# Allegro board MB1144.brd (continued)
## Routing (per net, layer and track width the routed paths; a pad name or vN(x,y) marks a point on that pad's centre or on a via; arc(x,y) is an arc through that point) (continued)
VDD_ADJ: length 204.3
  TOP w0.508: 45.31,21.16 C131.1 ; C131.1 44.56,21.97 ; C131.1 45.31,22.78 ; C133.1 45.69,20.78 ; C133.1 45.23,20.32 ; C133.1 45.69,19.86 ; R236.1 43.91,19.75 ; R236.1 44.49,19.18 ; R236.1 43.33,19.18 ; 45.65,19.01 U34.4 45.12,18.6 ; JP2.3 36.16,156.08 32.23,156.08 30.96,154.81 30.96,148.21 22.07,139.32 22.07,135.05 21.48,134.47 21.48,130.81 v3(20.97,130.3) ; v3(50.01,30.86) 51.66,32.51 51.66,38.99 46.58,44.07 30.83,44.07 28.92,45.97 22.45,45.97 v3(21.94,46.48)
  BOTTOM w0.508: v3(50.01,30.86) 45.94,26.8 45.94,24.26 v3(45.43,23.75) v3(44.67,23.75) v3(43.91,23.75) 37.56,17.4 TP13.1 ; v3(21.94,46.48) 21.94,47.88 23.21,49.15 23.21,56.39 14.57,65.02 14.57,68.71 15.84,69.98 15.84,76.33 17.24,77.72 17.24,85.72 12.03,90.93 12.03,107.31 17.62,112.9 17.62,114.81 20.8,117.98 20.8,130.12 v3(20.97,130.3)
VDD_IO: length 93.7
  TOP w0.254: U7.95 61.25,140.48 62.22,141.45 62.22,143.48 C35.2
  TOP w0.279: U7.131 51.82,126.15 51.66,125.98 C46.1
  TOP w0.508: v1(39.97,141.1) 39.97,137.54 33.75,131.32 33.75,125.22 34.26,124.71 34.26,119.25 v1(36.29,117.22) ; v1(62.33,144.53) 61.82,144.02 C35.2 ; v1(41.88,121.41) 41.88,123.57 43.4,125.09 47.47,125.09 48.1,125.73 C46.1 ; v1(44.04,142.11) 44.04,147.83 46.32,150.11 49.12,150.11 JP3.2 TP4.1 v1(58.77,152.4)
  BOTTOM w0.508: v1(58.77,152.4) 58.77,147.45 59.66,146.56 62.07,146.56 62.45,146.18 62.45,144.65 v1(62.33,144.53) ; v1(36.29,117.22) 36.29,118.24 38.83,120.78 41.37,120.78 41.88,121.28 v1(41.88,121.41) ; v1(39.97,141.1) 40.99,142.11 v1(44.04,142.11)
VDD_MCU: length 80.4
  TOP w0.254: U7.84 66.75,141.75 C38.2 ; C43.2 50.26,130.94 51.66,130.94 51.87,131.15 U7.121 ; U7.144 47.99,119.65 C48.2
  TOP w0.279: 76.17,127.64 75.79,127.64 75.3,127.15 U7.52 ; U7.17 62.75,116.76 C51.2 ; C41.2 77.69,138.43 76.41,137.15 U7.72 ; 54.32,141.6 54.32,140.34 54.75,139.91 U7.108 ; U7.39 75.41,120.65 ; U7.62 75.09,132.15 75.09,132.14 77.37,132.14 77.82,131.7 C42.1
  TOP w0.508: 76.17,127.64 76.3,127.76 v3(76.3,128.78) ; v3(78.45,132.46) 78.71,132.21 C42.1 ; v3(79.6,139.19) 78.96,138.56 C41.2 ; v3(51.91,143.89) C32.1 53.05,142.88 54.32,141.6 ; C43.2 49.37,131.06 v3(49.12,130.81) ; 75.41,120.65 75.41,120.65 77.57,118.49 C50.2 v3(79.09,117.6) ; C48.2 v3(47.85,118.36) ; v3(33.3,105.71) 33.3,105.54 33.05,105.28 23.72,105.28 JP11.2 JP11.3 ; v3(62.71,115.82) 62.07,115.82 C51.2 ; C38.2 v3(65.5,140.72)
  BOTTOM w0.508: v3(47.85,118.36) 47.85,117.23 45.66,115.03 41.15,115.03 33.3,107.19 v3(33.3,105.71)
VDD_USB: length 39.5
  TOP w0.254: 55.59,140.97 55.59,140.34 55.72,140.21 55.72,139.23 U7.106
  TOP w0.508: 55.59,140.97 55.47,141.1 C36.2 C33.1 v1(54.32,143)
  BOTTOM w0.508: v1(54.32,143) 47.21,143 42.01,148.21 42.01,155.96 41.28,156.68 38.28,156.68 36.8,158.17 JP1.2 TP2.1
VDDA: length 39.9
  TOP w0.279: U7.33 70.75,118.61 71.52,119.38 v3(72.74,119.38)
  TOP w0.508: C60.2 88.06,106.17 ; C60.2 87.6,106.63 ; C60.2 87.6,105.71 ; 88.23,110.31 CN10.2 ; CN10.2 88.23,112.19 ; CN10.2 89.17,111.25 ; CN10.2 87.29,111.25 ; L1.2 91.79,106.88 ; L1.2 91.79,105.71 ; L1.2 91.17,106.3 ; C59.1 89.17,108.33 ; C59.1 87.55,108.33 ; C59.1 88.36,109.27 ; C59.1 88.36,107.39 ; 91.15,108.28 TP8.1 ; TP8.1 91.15,110.16 ; TP8.1 92.09,109.22 ; TP8.1 90.21,109.22
  BOTTOM w0.508: v3(72.74,119.38) 72.87,119.25 86.33,119.25 86.84,118.75 86.84,114.81 88.23,113.41 CN10.2
A0: length 208.7
  TOP w0.102: U5.E2 102.45,143.61 102.97,143.1 102.97,142.72 v4(102.84,142.6)
  TOP w0.127: v1(59.65,130.87) 58.9,130.12 58.9,127.13 59.25,126.77 U7.10 ; CN6.25 v1(28.16,121.41) ; U2.A3 82.94,152.3 82.61,152.63 81.6,152.63 80.92,153.31 v1(80.92,153.37) ; U21.47 53.39,70.44 52.67,69.72 51.78,69.72 51.02,70.48 35.66,70.48 v1(35.53,70.61)
  BOTTOM w0.127: v4(102.84,142.6) 102.97,142.72 102.97,143.62 102.86,143.73 102.86,148.31 101.34,149.83 101.34,152.83 99.92,154.25 99.92,157.35 97.12,160.15 91.99,160.15 89,157.15 89,154.81 88.77,154.58 84.22,154.58 83.61,155.19 82.14,155.19 81.12,154.18 81.12,153.64 80.92,153.44 v1(80.92,153.37) 80.87,153.31 80.87,153.29 80.36,152.78 79.34,152.78 77.31,150.75 77.31,142.11 73.73,138.53 72.84,138.53 71.09,136.78 71.09,136.17 66.74,131.83 60.6,131.83 v1(59.65,130.87) 57.81,129.03 46.96,129.03 46.58,129.41 44.29,129.41 44.04,129.16 39.08,129.16 32,122.07 28.82,122.07 v1(28.16,121.41) 26.64,119.89 26.64,111.63 27.74,110.53 27.74,101.57 26.77,100.6 26.77,98.04 26.48,97.76 26.48,95.25 27.07,94.67 27.07,93.19 29.76,90.5 29.76,77.39 30.68,76.48 30.68,74.95 33.5,72.14 34,72.14 v1(35.53,70.61)
A0_1DELAY: length 12.5
  TOP w0.127: U21.40 56.89,70.1 56.61,69.82 v1(56.61,69.82) ; U21.2 53.39,65.32 v1(52.67,66.04)
  BOTTOM w0.127: 52.42,63.63 52.04,64.01 52.04,65.41 v1(52.67,66.04) 56.36,69.72 56.51,69.72 v1(56.61,69.82)
A0_2DELAY: length 3.8
  TOP w0.127: v1(56.48,62.31) 56.48,62.36 56.89,62.77 U21.9
  BOTTOM w0.127: 54.71,63.27 54.71,63.12 55.52,62.31 v1(56.48,62.31)
A1: length 225.2
  TOP w0.102: v4(101.77,142.49) 101.37,142.49 100.98,142.88 100.98,143.6 101.44,144.06 U5.D2
  TOP w0.127: v1(39.62,67.79) 43.15,64.26 48.41,64.26 52.04,60.63 58.29,60.63 58.72,61.06 v1(58.72,62.15) ; v1(81.55,153.37) 81.91,153.01 82.92,153.01 U2.A4 ; v1(59.65,130.17) 59.28,129.8 59.28,127.38 59.75,126.91 U7.11 ; CN6.26 v1(29.56,121.41) ; v1(59.15,69.6) 58.39,70.35 U21.37
  BOTTOM w0.127: v4(101.77,142.49) 101.77,142.6 101.8,142.62 101.8,143.54 102.58,144.32 102.58,148.08 100.96,149.71 100.96,152.65 99.54,154.08 99.54,157.18 96.95,159.77 92.17,159.77 89.38,156.97 89.38,156.26 89.25,156.13 89.25,155.63 89.22,155.6 89.22,154.71 88.82,154.31 84.04,154.31 83.41,154.94 82.9,154.94 82.77,154.81 82.39,154.81 81.76,154.18 81.76,153.62 81.55,153.42 v1(81.55,153.37) 81.5,153.31 81.5,153.29 80.61,152.4 79.6,152.4 77.69,150.5 77.69,141.94 73.91,138.15 73.02,138.15 71.6,136.73 71.6,136.42 71.62,136.4 71.62,136.09 66.97,131.44 60.92,131.44 v1(59.65,130.17) 58.13,128.65 46.7,128.65 46.32,129.03 44.8,129.03 44.55,128.78 39.34,128.78 31.97,121.41 v1(29.56,121.41) 28.92,121.41 27.02,119.51 27.02,111.89 28.12,110.79 28.12,101.3 27.15,100.33 27.15,97.79 26.86,97.51 26.86,95.41 27.45,94.82 27.45,93.37 30.14,90.68 30.14,77.56 31.12,76.58 31.12,75.27 33.75,72.64 34.77,72.64 v1(39.62,67.79) ; v1(58.72,62.15) 58.13,62.74 58.13,64.14 SB51.1 58.9,67.56 59.15,67.82 v1(59.15,69.6)
A1_1DELAY: length 4.5
  TOP w0.127: v1(59.89,65.81) 58.74,65.81 58.39,65.46 U21.12
  BOTTOM w0.127: SB50.1 60.29,65.41 v1(59.89,65.81)
A1_BUF: length 31.2
  TOP w0.127: U22.24 82.68,65.12 82.39,65.41 71.85,65.41 71.18,64.73 U22.1 71.18,62.58 R166.2 68.75,62.1 67.05,60.4 62.5,60.4 v1(61.94,60.96)
  BOTTOM w0.127: v1(61.94,60.96) 61.94,63.04 61.61,63.37 58.9,63.37
A2: length 129
  TOP w0.102: v1(82.26,153.92) 82.41,153.78 U2.A5 ; v4(99.92,143.59) 99.96,143.62 99.99,143.62 100.43,144.06 U5.C2
  TOP w0.127: v1(61.31,130.81) 61.18,130.81 60.25,129.88 U7.12 ; CN6.32 v1(29.43,117.6)
  BOTTOM w0.127: v4(99.92,143.59) 99.94,143.59 99.98,143.62 101.43,143.62 102.2,144.4 102.2,147.96 99.97,150.19 99.97,151.76 99.16,152.58 99.16,157 96.77,159.38 92.35,159.38 89.76,156.79 89.76,156.08 89.63,155.96 89.63,155.45 89.5,155.32 89.5,154.56 88.97,154.03 83.94,154.03 83.79,154.18 82.52,154.18 v1(82.26,153.92) 82.26,153.03 81.88,152.65 81.5,152.65 80.87,152.02 79.98,152.02 78.07,150.11 78.07,141.76 74.09,137.77 73.2,137.77 72,136.58 72,135.92 67.15,131.06 61.56,131.06 v1(61.31,130.81) 60.93,130.81 58.39,128.27 52.93,128.27 51.86,127.2 40.05,127.2 30.45,117.6 v1(29.43,117.6)
A3: length 130.5
  TOP w0.102: U5.A2 98,143.61 v4(97.99,143.61)
  TOP w0.127: v1(81.96,152.17) 82.24,151.89 83.15,151.89 83.41,152.15 83.56,152.15 U2.B3 ; v1(61.31,130.18) 60.75,129.61 U7.13 ; CN6.34 v1(29.43,116.33)
  BOTTOM w0.127: v4(97.99,143.61) 98.44,143.15 99.13,143.15 99.4,143.42 99.4,143.68 99.76,144.04 100.5,144.04 100.65,143.89 101.37,143.89 101.9,144.42 101.9,147.5 99.59,149.81 99.59,151.59 98.77,152.4 98.77,156.82 96.59,159 92.53,159 90.14,156.62 90.14,155.91 90.01,155.78 90.01,155.37 89.73,155.09 89.73,154.46 89,153.72 83.51,153.72 v1(81.96,152.17) 81.63,152.17 81.1,151.64 80.16,151.64 78.45,149.94 78.45,141.58 74.26,137.39 73.37,137.39 72.38,136.4 72.38,135.74 67.33,130.68 61.82,130.68 v1(61.31,130.18) 60.93,130.18 58.64,127.89 53.69,127.89 51.78,125.98 50.51,125.98 50.13,125.6 39.72,125.6 30.45,116.33 v1(29.43,116.33)
A4: length 127.3
  TOP w0.102: U2.B4 83.69,152.94 83.41,152.65 v5(83.33,152.65) ; U5.B2 v4(98.99,143.6)
  TOP w0.127: CN6.37 27.4,113.79 v1(28.29,114.68) ; U7.14 61.25,129.48 v1(61.31,129.54)
  BOTTOM w0.127: v4(98.99,143.6) 99.76,144.37 100.5,144.37 100.76,144.12 101.26,144.12 101.64,144.5 101.64,147.36 99.21,149.8 99.21,151.41 98.39,152.22 98.39,156.64 96.41,158.62 92.7,158.62 90.52,156.44 90.52,155.73 90.39,155.6 90.39,155.19 90.04,154.84 90.04,154.43 89,153.39 84.07,153.39 v5(83.33,152.65) 83.08,152.65 82.14,151.71 81.73,151.71 81.27,151.26 80.33,151.26 78.84,149.76 78.84,141.4 67.74,130.3 62.07,130.3 v1(61.31,129.54) 59.28,127.51 53.94,127.51 51.28,124.84 40.23,124.84 30.19,114.81 28.42,114.81 v1(28.29,114.68)
A5: length 121.8
  TOP w0.102: v5(84.84,152.65) 84.47,152.28 U2.C3
  TOP w0.127: CN6.38 30.32,113.79 v1(29.81,114.3) ; U5.D3 101.45,145.04 v4(100.93,144.53) ; v1(62.07,129.54) 61.75,129.22 U7.15
  BOTTOM w0.127: v4(100.93,144.53) 101.39,144.98 101.39,147.19 98.83,149.76 98.83,151.23 98.01,152.04 98.01,156.46 96.23,158.24 92.88,158.24 90.9,156.26 90.9,155.37 90.32,154.79 90.32,154.31 89.12,153.11 85.3,153.11 v5(84.84,152.65) 84.17,152.65 83.71,152.2 83.03,152.2 82.16,151.33 81.91,151.33 81.45,150.88 80.51,150.88 79.22,149.58 79.22,141.22 67.91,129.92 62.45,129.92 v1(62.07,129.54) 59.66,127.13 54.1,127.13 51.43,124.46 40.61,124.46 30.45,114.3 v1(29.81,114.3)
A6: length 98.6
  TOP w0.102: U5.C3 100,145.06 99.4,144.45 98.11,144.45 97.91,144.25 97.35,144.25 v1(97.12,144.02)
  TOP w0.127: U2.C4 84.44,152.8 84.07,152.43 84.07,152.16 83.79,151.88 83.55,151.88 83.34,151.68 83.34,151.43 83.04,151.13 82.8,151.13 82.52,150.85 82.52,149.05 81.5,148.03 v4(81.4,148.03) ; CN7.17 v1(97.12,126.49) ; v1(71.98,128.52) 71.98,126.9 72.73,126.15 U7.50
  BOTTOM w0.127: v1(97.12,144.02) 96.92,144.22 96.92,147.96 96.11,148.77 96.11,155.57 95.35,156.34 93.77,156.34 92.81,155.37 92.81,154.48 92.27,153.95 92.27,153.72 89.94,151.38 87.42,151.38 87.04,151 85.82,151 85.69,151.13 84.55,151.13 84.17,150.75 84.17,150.62 81.58,148.03 v4(81.4,148.03) 81.12,147.75 81.12,138.73 79.75,137.36 78.15,137.36 73.6,132.82 73.6,132.51 73.63,132.49 73.63,131.44 71.98,129.79 v1(71.98,128.52) 72.1,128.4 72.74,128.4 73.25,127.89 74.9,127.89 75.41,127.38 90.77,127.38 91.66,126.49 v1(97.12,126.49)
A7: length 101.6
  TOP w0.102: v4(97.5,145.03) 97.53,145.06 U5.A3
  TOP w0.127: CN7.18 v1(98.27,126.49) ; v1(81.25,149.28) 81.22,149.3 81.22,150.14 79.09,152.27 79.09,153.92 79.34,154.18 81.38,154.18 82.14,153.42 84.68,153.42 85.06,153.03 U2.D4 ; U7.53 74.29,127.64 72.87,127.64 v1(72.61,127.89)
  BOTTOM w0.127: v4(97.5,145.03) 97.4,145.14 97.4,150.34 96.49,151.26 96.49,155.75 95.52,156.72 93.59,156.72 92.42,155.55 92.42,154.66 91.89,154.13 91.89,153.9 89.76,151.76 87.22,151.76 86.71,151.26 85.95,151.26 85.82,151.38 84.4,151.38 83.41,150.39 83.38,150.39 82.34,149.35 81.32,149.35 v1(81.25,149.28) 81.15,149.28 80.74,148.87 80.74,140.03 80.11,139.4 80.11,138.56 79.41,137.86 78.09,137.86 71.29,131.06 71.29,128.57 71.98,127.89 v1(72.61,127.89) 72.99,127.51 74.64,127.51 75.15,127 90.52,127 91.66,125.86 97.63,125.86 v1(98.27,126.49)
A8: length 76.7
  TOP w0.102: 96.87,147.59 98,147.59 98.11,147.47 98.86,147.47 U5.B6
  TOP w0.127: v1(72.49,129.41) 72.49,129.03 73.37,128.14 74.3,128.14 U7.54 ; 96.87,147.59 96.04,147.59 94.15,149.48 91.04,149.48 89.77,150.75 89.48,150.75 v4(89.3,150.93) 88.84,151.38 88.34,151.38 U2.H2 ; CN7.16 v1(98.14,127.76)
  BOTTOM w0.127: v4(89.3,150.93) 89.12,150.75 88.82,150.75 88.69,150.62 84.73,150.62 81.54,147.43 81.54,138.6 79.93,136.98 78.33,136.98 74.01,132.66 74.01,131.19 72.49,129.67 v1(72.49,129.41) 72.49,129.29 73.5,128.27 75.15,128.27 75.66,127.76 91.03,127.76 91.66,127.13 97.5,127.13 v1(98.14,127.76)
A9: length 74.8
  TOP w0.127: CN7.14 98.37,129.03 98.16,128.83 v1(98.16,128.73) ; v1(73.12,129.41) 73.12,129.03 73.51,128.65 U7.55 ; U5.A6 98.05,148.45 96.42,148.45 94.63,150.24 91.62,150.24 90.75,151.12 v4(90.75,151.33) 90.53,151.33 89.59,152.27 88.2,152.27 U2.H3
  BOTTOM w0.127: v1(98.16,128.73) 97.71,128.27 96.17,128.27 96.04,128.14 75.91,128.14 75.28,128.78 73.63,128.78 73.12,129.29 v1(73.12,129.41) 73.12,129.67 74.39,130.94 74.39,132.28 78.71,136.6 80.11,136.6 82.26,138.76 82.26,147.6 84.4,149.73 84.7,149.73 84.73,149.71 87.89,149.71 88.55,150.37 89.78,150.37 v4(90.75,151.33)
A10: length 75.1
  TOP w0.102: U5.C6 99.84,148.67 99.84,149.21 99.59,149.47 96.87,149.47
  TOP w0.127: v1(98.14,129.9) 98.55,130.3 CN7.12 ; U7.56 v1(75.53,129.15) ; 96.87,149.47 96.73,149.47 95.19,151 92.07,151 v4(91.97,151.1) 91.97,151.69 90.52,153.14 89.35,153.14 89.33,153.11 88.44,153.11 88.35,153.03 U2.H4
  BOTTOM w0.127: v4(91.97,151.1) 91.97,151.05 90.9,149.99 88.72,149.99 88.06,149.33 84.55,149.33 82.65,147.42 82.65,138.58 80.28,136.22 78.89,136.22 74.77,132.11 74.77,129.79 75.42,129.15 v1(75.53,129.15) 75.65,129.15 75.79,129.29 97.53,129.29 v1(98.14,129.9)
A11: length 85.6
  TOP w0.102: U5.D6 101.83,148.44 101.83,150.58 101.49,150.93 101.49,151.13
  TOP w0.127: v1(96.79,129.92) 96.41,130.3 CN7.11 ; U7.57 74.88,129.65 74.9,129.67 75.79,129.67 76.04,129.92 v1(76.17,129.92) ; 101.49,151.13 101.49,154.03 102.99,155.52 102.99,155.88 102.69,156.18 99.38,156.18 98.34,155.14 98.34,154.76 98.37,154.74 98.37,154.46 98.34,154.43 98.34,154.41 95.78,151.84 v4(93.21,151.84) 93.19,151.87 92.91,151.87 90.85,153.92 88.34,153.92 U2.H5
  BOTTOM w0.127: v4(93.21,151.84) 93.21,151.69 91.13,149.61 88.89,149.61 88.23,148.95 84.73,148.95 83.03,147.24 83.03,138.4 80.46,135.84 79.06,135.84 75.15,131.93 75.15,130.94 v1(76.17,129.92) v1(96.79,129.92)
A12: length 112.9
  TOP w0.102: U5.B7 98.89,148.5 98.89,147.96 98.61,147.68 98.22,147.68 97.91,147.98 96.87,147.98 ; U2.G3 87.44,152.26 87.81,151.89 89,151.89
  TOP w0.127: 96.87,147.98 96.31,147.98 94.43,149.86 91.37,149.86 v1(90.65,150.58) 89.34,151.89 89,151.89 ; v1(86.71,158.62) 87.22,158.12 92.68,158.12 94.58,156.21 v1(94.58,155.88) ; U7.87 65.25,138.3 v1(65.69,137.86) ; CN6.13 v1(28.42,129.03)
  BOTTOM w0.127: v1(90.65,150.58) 90.81,150.58 92.04,151.82 92.04,152.37 93.03,153.37 93.03,153.59 93.57,154.13 93.57,154.64 94.58,155.65 v1(94.58,155.88) ; v1(28.42,129.03) 28.92,129.54 32.73,129.54 37.69,134.49 58.01,134.49 58.13,134.37 64.1,134.37 65.25,135.51 65.25,137.41 v1(65.69,137.86) 66.77,138.94 69.31,138.94 73.37,143 73.37,143.13 74.42,144.17 74.42,144.7 74.9,145.19 74.9,155.07 77.95,158.12 78.96,158.12 79.22,157.86 79.72,157.86 79.98,158.12 86.2,158.12 v1(86.71,158.62)
A13: length 107.6
  TOP w0.127: U2.G4 87.8,152.67 88.47,152.67 88.56,152.76 90.34,152.76 91.28,151.82 v1(91.28,151.71) 91.54,151.46 91.54,150.88 91.79,150.62 94.96,150.62 96.53,149.06 U5.A7 ; CN6.12 29.81,130.3 v1(29.56,130.05) ; U7.88 64.75,138.15 v1(64.93,137.97) ; v1(85.69,158.62) 86.07,158.62 86.96,157.73 92.3,157.73 93.95,156.08 v1(93.95,155.85)
  BOTTOM w0.127: v1(93.95,155.85) 93.92,155.83 93.92,155.8 93.19,155.07 93.19,154.31 92.65,153.77 92.65,153.54 91.28,152.17 v1(91.28,151.71) ; v1(85.69,158.62) 85.31,159 82.14,159 81.76,159.38 78.45,159.38 74.52,155.45 74.52,145.36 74.03,144.88 74.03,144.42 72.99,143.38 72.99,143.26 69.18,139.45 66.4,139.45 v1(64.93,137.97) 64.87,137.91 64.87,135.76 63.85,134.75 58.39,134.75 58.26,134.87 37.43,134.87 32.61,130.05 v1(29.56,130.05)
A14: length 118
  TOP w0.127: v1(101.62,155.73) 100.2,155.73 98.65,154.18 98.65,152.22 99.92,150.95 99.92,150.01 100.43,149.5 100.43,149.08 U5.C7 ; CN6.14 v1(29.56,129.03) ; U7.89 64.25,137.96 64.88,137.33 65.5,137.33 v1(65.73,137.1) ; v1(85.44,157.61) 84.93,157.1 84.93,155.83 84.55,155.45 84.55,155.07 84.8,154.81 84.8,153.67 85.06,153.42 85.31,153.42 85.57,153.16 85.57,152.91 85.82,152.65 86.32,152.65 U2.F3
  BOTTOM w0.127: v1(29.56,129.03) 32.86,129.03 37.94,134.11 57.75,134.11 57.88,133.99 64.36,133.99 65.73,135.36 v1(65.73,137.1) 65.73,137.19 67.1,138.56 69.56,138.56 72.08,141.07 72.76,141.07 74.8,143.1 74.8,144.53 75.28,145.01 75.28,153.67 78.07,156.46 78.96,156.46 80.23,157.73 85.31,157.73 v1(85.44,157.61) 86.33,157.61 86.84,158.12 87.73,158.12 91.15,161.54 97.96,161.54 101.44,158.06 101.44,155.93 101.62,155.75 v1(101.62,155.73)
A15: length 108
  TOP w0.102: 96.87,149.99 96.95,149.91 97.96,149.91 98.2,149.67 99.83,149.67 100.04,149.45 100.04,148.87 100.3,148.62 101.01,148.62 U5.D7
  TOP w0.127: v1(87.34,158.75) 87.6,158.5 92.93,158.5 95.22,156.21 v1(95.22,155.83) ; 96.87,149.99 95.47,151.38 92.6,151.38 v1(92.42,151.56) 92.42,151.79 90.67,153.54 88.46,153.54 88.33,153.42 87.19,153.42 86.8,153.03 U2.F4 ; v1(64.23,140.46) 63.72,139.95 63.72,139.22 U7.90 ; CN6.10 32.73,131.57 v1(33.5,132.33)
  BOTTOM w0.127: v1(87.34,158.75) 86.71,159.38 82.52,159.38 82.14,159.77 78.2,159.77 74.14,155.7 74.14,145.54 73.65,145.06 73.65,144.68 72.49,143.51 72.49,143.38 70.45,141.35 65.12,141.35 v1(64.23,140.46) 63.85,140.08 63.72,140.08 61.18,137.54 59.66,137.54 57.75,135.64 36.8,135.64 v1(33.5,132.33) ; v1(95.22,155.83) 95.22,155.73 93.95,154.46 93.95,153.95 93.52,153.52 93.52,153.29 92.42,152.2 v1(92.42,151.56)
A16: length 142.1
  TOP w0.102: 102.04,150.69 102.04,149.47 U5.E7
  TOP w0.127: v1(86.02,86.74) 85.54,86.26 85.54,84.76 84.47,83.69 72.03,83.69 68.98,80.64 68.58,80.64 ; 102.04,150.69 102.04,153.45 102.03,153.47 102.03,153.87 v1(102.99,154.84) 102.99,154.86 103.37,155.24 103.37,156.06 102.86,156.57 99.21,156.57 97.96,155.32 97.96,154.58 95.65,152.27 93.06,152.27 91.15,154.18 91.15,154.61 90.76,155 89.67,155 89.1,155.57 88.28,155.57 87.79,155.08 87.79,154.37 87.6,154.18 87.34,154.18 87.09,153.92 87.09,153.67 86.84,153.42 86.33,153.42 U2.E4
  BOTTOM w0.127: v1(102.99,154.84) 102.99,154.36 103.57,153.77 103.57,152.81 105,151.38 106.69,151.38 107.12,150.95 108.83,150.95 109.65,150.14 109.65,141.88 108.88,141.12 108.88,139.32 107.03,137.46 106.45,137.46 105.76,136.78 105.76,136.4 105.25,135.89 105.25,109.35 105.63,108.97 105.63,99.52 104.72,98.6 104.72,98.58 103.85,97.71 103.85,92.46 98.14,86.74 v1(86.02,86.74)
A17: length 109.6
  TOP w0.102: U5.B3 99.04,144.65 97.92,144.65 97.77,144.5 96.87,144.5
  TOP w0.127: R151.1 74.36,83.29 84.63,83.29 85.92,84.58 85.92,85.95 86.58,86.61 86.58,88.9 85.95,89.53 v1(85.95,89.66) ; U2.D3 85.59,151.88 85.59,151.36 85.81,151.14 86.1,151.14 86.33,150.91 86.33,150.5 86.58,150.24 86.58,149.1 89.15,146.53 89.15,143.64 90.44,142.34 91.94,142.34 v1(92.02,142.27) 93.26,142.27 93.92,141.6 94.08,141.6 94.71,142.24 94.71,142.37 96.84,144.5 96.87,144.5
  BOTTOM w0.127: v1(85.95,89.66) 86.96,90.68 88.36,90.68 89.63,91.95 94.08,91.95 98.65,96.52 98.65,99.31 100.5,101.17 100.5,109.25 101.06,109.8 101.06,135.2 98.34,137.92 94.84,137.92 91.59,141.17 91.59,141.86 91.99,142.27 v1(92.02,142.27)
A18: length 110.6
  TOP w0.102: U5.C4 99.83,145.44 97.15,145.44 96.87,145.16
  TOP w0.127: 96.87,145.16 95.37,143.66 v1(93.87,143.66) 93.69,143.48 91.79,143.48 91.21,144.07 91.21,147.65 88.49,150.37 88.49,150.4 88.19,150.7 U2.H1 ; v1(86.58,89.66) 86.96,89.28 86.96,86.44 86.3,85.78 86.3,84.4 84.8,82.91 75.92,82.91 73.66,80.64
  BOTTOM w0.127: v1(93.87,143.66) 93.49,143.28 93.49,141.81 95.85,139.45 99.05,139.45 102.58,135.92 102.58,108.86 102.05,108.33 102.05,100.18 100.81,98.93 100.81,96.01 98.01,93.22 98.01,91.31 97.5,90.81 93.82,90.81 93.31,90.3 87.22,90.3 v1(86.58,89.66)
A19: length 91.7
  TOP w0.102: 96.87,146.56 96.98,146.44 100.83,146.44 U5.D5
  TOP w0.127: U2.G2 87.58,151.53 87.98,151.13 88.33,151.13 88.54,150.93 88.54,150.9 91.59,147.85 91.59,145.54 91.79,145.34 v1(92.02,145.34) 92.22,145.34 92.78,145.9 95.57,145.9 96.23,146.56 96.87,146.56 ; R150.1 R139.1 92.04,89.79 92.93,90.68 v1(92.93,90.81)
  BOTTOM w0.127: v1(92.02,145.34) 92.2,145.34 92.68,144.86 92.68,141.78 92.65,141.76 92.65,141.38 95.35,138.68 98.7,138.68 101.82,135.56 101.82,109.4 101.26,108.84 101.26,100.66 99.66,99.06 99.66,96.14 94.71,91.19 93.31,91.19 v1(92.93,90.81)
A20: length 93.9
  TOP w0.102: U5.D4 100.93,145.54 v4(100.91,145.54)
  TOP w0.127: U2.H6 88.11,154.61 88.11,155.07 88.39,155.35 88.89,155.35 89.76,154.48 v5(90.71,154.48) ; R100.1 53.94,111.38 R84.1 53.44,111.63 v1(52.42,112.65)
  BOTTOM w0.127: v4(100.91,145.54) 100.91,147.33 98.44,149.8 98.44,151.05 97.63,151.87 97.63,156.29 96.06,157.86 93.06,157.86 91.28,156.08 91.28,155.19 90.71,154.62 v5(90.71,154.48) 90.71,154.24 89.33,152.86 86.79,152.86 86.2,152.27 84.17,152.27 83.81,151.92 83.18,151.92 81.76,150.5 80.69,150.5 79.6,149.4 79.6,141.05 68.09,129.54 62.71,129.54 59.53,126.36 59.53,125.53 56.23,122.22 56.23,119.63 52.29,115.7 52.29,112.78 v1(52.42,112.65)
A21: length 85.9
  TOP w0.102: U5.C5 100.41,147.06 v4(99.92,147.55) ; v5(86.32,151.92) 86.28,151.96 86.28,151.99 85.99,152.28 U2.E3
  TOP w0.127: v1(54.71,114.43) 54.45,114.17 54.45,112.52 55.21,111.76 R85.1 R101.1
  BOTTOM w0.127: v1(54.71,114.43) 54.83,114.55 54.83,117.47 56.61,119.25 56.61,122.05 59.91,125.35 59.91,126.11 62.96,129.16 68.27,129.16 79.98,140.87 79.98,149.22 80.87,150.11 81.98,150.11 83.56,151.69 83.94,151.69 84.27,152.02 86.21,152.02 v5(86.32,151.92) 86.95,152.55 89.43,152.55 91.1,154.23 91.1,154.46 91.66,155.02 91.66,155.91 93.24,157.48 95.88,157.48 97.25,156.11 97.25,151.69 98.05,150.89 98.05,149.42 v4(99.92,147.55)
A22: length 81.6
  TOP w0.102: U5.B8 98.8,150.71 97.63,150.71 v4(97.52,150.83)
  TOP w0.127: R102.1 56.74,110.49 R86.1 55.98,112.39 55.98,114.3 v1(55.85,114.43)
  BOTTOM w0.127: v1(55.85,114.43) 55.47,114.81 55.47,117.47 56.99,119 56.99,121.87 60.29,125.17 60.29,125.86 63.21,128.78 68.45,128.78 80.36,140.69 80.36,149.05 81.05,149.73 82.16,149.73 83.89,151.46 84.04,151.46 84.35,151.76 85.82,151.76 86.07,151.51 86.46,151.51 87.09,152.15 89.58,152.15 91.48,154.05 91.48,154.28 92.04,154.84 92.04,155.73 93.41,157.1 95.7,157.1 96.87,155.93 96.87,151.47 v4(97.52,150.83)
A23: length 99.2
  TOP w0.127: R149.1 R138.1 89.76,86.84 v1(90.42,87.5) ; v1(102.53,155.7) 102.03,155.19 100.22,155.19 99.03,154 99.03,152.7 100.45,151.28 U5.C8
  BOTTOM w0.127: v1(90.42,87.5) 94.46,87.5 95.35,88.39 99.16,88.39 103.47,92.71 103.47,97.89 104.34,98.76 104.34,98.78 105.25,99.69 105.25,108.79 104.87,109.17 104.87,136.47 106.24,137.85 106.85,137.85 108.5,139.5 108.5,141.3 109.26,142.06 109.26,149.96 108.65,150.57 106.95,150.57 106.65,150.88 104.92,150.88 103.19,152.6 103.19,153.59 102.53,154.25 v1(102.53,155.7)
AIN_1: length 5.1
  TOP w0.127: R186.2 R183.1 59.66,46.61 60.04,46.99 60.04,48.51 60.32,48.8 U23.10
BL_VDD: length 16.6
  TOP w0.508: L4.1 92.3,31.11 C115.1 94.58,31.11 95.6,32.13 C113.2 v1(96.87,32.13) ; v1(94.2,35.69) R259.1
  BOTTOM w0.508: CN19.28 99.88,30.99 98.01,30.99 v1(96.87,32.13) 94.2,34.8 v1(94.2,35.69)
BOOT0: length 66.5
  TOP w0.127: R67.1 47.47,123.44 v1(48.86,123.44) 49.66,122.65 U7.138 55.88,122.65 v1(57.5,121.03) ; CN7.20 v1(98.27,125.22)
  BOTTOM w0.127: v1(57.5,121.03) 57.5,121.82 60.67,124.99 60.67,125.6 62.83,127.76 66.64,127.76 68.8,125.6 78.71,125.6 79.34,126.24 89.88,126.24 91.54,124.59 97.38,124.59 98.01,125.22 v1(98.27,125.22) ; JP8.1 43.66,123.44 v1(48.86,123.44)
COMP2_INP: length 61.5
  TOP w0.508: 86.36,98.42 87.48,99.54 92.04,99.54 96.01,95.58 v1(108.68,95.58)
  BOTTOM w0.508: JP7.3 110.92,128.6 110.92,127.89 110.41,127.38 110.41,125.04 109.59,124.23 109.59,115.75 107.54,113.69 107.54,112.04 109.21,110.36 109.21,96.09 108.71,95.58 v1(108.68,95.58)
COMP2_OUT: length 11.4
  BOTTOM w0.127: 48.26,98.42 48.25,98.42 48.05,98.63 48.05,109.27 TP6.1
D0: length 153.9
  TOP w0.127: 76.2,80.64 76.2,81.31 77.31,82.42 v1(84.25,82.42) 84.96,82.42 86.68,84.15 86.68,85.6 87.47,86.39 v1(87.47,87.88) ; v1(82.01,72.39) 82.18,72.22 U22.26 ; v1(108.3,141.81) 108.1,142.01 108.1,142.02 107.56,142.56 104.2,142.56 103.92,142.84 103.92,143.17 103.63,143.47 103.3,143.47 102.97,143.8 102.97,144.55 102.46,145.06 U5.E3 ; v1(84.93,160.27) 84.93,158.88 83.28,157.23 83.28,155.7 83.69,155.29 U2.B6
  BOTTOM w0.127: v1(87.47,87.88) 87.6,88.01 94.33,88.01 95.22,88.9 98.9,88.9 103.09,93.09 103.09,98.07 103.96,98.93 103.96,98.96 104.87,99.87 104.87,108.58 104.49,108.97 104.49,136.65 106.06,138.23 106.67,138.23 108.1,139.65 108.1,141.6 v1(108.3,141.81) 108.88,142.39 108.88,149.78 108.48,150.19 106.83,150.19 106.52,150.5 104.74,150.5 102.81,152.43 102.81,153.42 102.15,154.08 102.15,155.12 102.08,155.19 102.08,157.99 98.14,161.93 85.87,161.93 84.93,160.99 v1(84.93,160.27) ; v1(82.01,72.39) 84.73,75.11 84.73,81.56 84.25,82.04 v1(84.25,82.42)
D1: length 142.6
  TOP w0.127: 78.74,80.64 78.74,80.93 79.75,81.94 v1(82.62,81.94) 85.11,81.94 87.06,83.9 87.06,85.42 87.98,86.33 v1(87.98,89.79) ; U22.27 81.68,71.96 81.25,72.39 v1(81.25,72.52) ; U5.H3 105.76,145.06 105.84,144.98 106.8,144.98 v1(107,145.19) 107,145.34 108.25,146.58 108.25,148.97 107.77,149.45 107.77,150.14 106.88,151.03 106.88,153.26 106.85,153.29 106.85,154.66 105.89,155.63 105.89,157 104.01,158.88 97.94,158.88 95.68,156.62 95.68,155.65 95.37,155.35 93.8,155.35 91.79,157.35 86.71,157.35 85.95,158.12 84.93,158.12 83.66,156.84 83.66,155.96 84.04,155.57 84.04,154.16 84.42,153.78 U2.C5
  BOTTOM w0.127: v1(107,145.19) 107.28,144.91 107.28,143.1 106.57,142.39 106.57,140.36 105.96,139.75 105.1,139.75 102.97,137.62 102.97,107.95 103.35,107.57 103.35,100.84 101.44,98.93 101.44,95.89 98.39,92.84 98.39,91.06 97.76,90.42 94.08,90.42 93.44,89.79 v1(87.98,89.79) ; v1(82.62,81.94) 82.9,81.66 82.9,74.17 v1(81.25,72.52)
D2: length 233.2
  TOP w0.102: v4(103.98,148.59) 103.35,148.59 103.07,148.31 103.07,146.68 U5.E4
  TOP w0.127: v1(55.21,132.84) 55.21,133.35 53.92,134.65 U7.114 ; U22.29 80.68,72.81 80.94,73.08 80.94,73.63 80.66,73.91 61.41,73.91 60.6,73.1 56.2,73.1 55.87,72.77 53.21,72.77 52.7,72.26 51.35,72.26 50.59,71.5 31.85,71.5 v1(31.13,70.79) ; U2.C6 84.42,154.53 84.3,154.66 v1(84.3,156.59) ; v1(28.34,126.49) CN6.17 24.4,126.49 v1(24.38,126.47)
  BOTTOM w0.127: v1(31.13,70.79) 31.13,71.2 27.73,74.6 27.73,88.16 22.93,92.97 22.93,95.81 20.92,97.82 20.92,100.84 23.59,103.5 23.59,110.87 23.08,111.38 23.08,113.28 24.1,114.3 24.1,125.96 24.38,126.24 v1(24.38,126.47) ; v4(103.98,148.59) 103.35,149.22 103.35,151.33 102.43,152.25 102.43,153.24 101.77,153.9 101.77,154.94 101.06,155.65 101.06,157.89 97.78,161.16 91.41,161.16 87.98,157.73 87.09,157.73 85.69,156.34 84.55,156.34 v1(84.3,156.59) 81.12,156.59 76.04,151.51 76.04,144.65 75.56,144.17 75.56,142.72 73.02,140.18 72.31,140.18 65.35,133.22 59.15,133.22 58.77,132.84 v1(55.21,132.84) 54.58,132.84 54.2,132.46 50.26,132.46 50.13,132.33 49.12,132.33 48.48,132.97 38.7,132.97 32.81,127.08 28.92,127.08 v1(28.34,126.49)
D3: length 200.5
  TOP w0.127: U7.115 53.65,134.15 v1(54.45,133.35) ; CN6.16 v1(29.69,127.76) ; U5.H4 105.45,146.06 107.18,146.06 107.77,146.65 107.77,148.89 107.38,149.28 107.38,149.96 106.47,150.88 106.47,154.48 105.51,155.45 105.51,156.82 103.83,158.5 98.11,158.5 96.06,156.44 96.06,155.47 95.55,154.97 93.59,154.97 91.59,156.97 85.69,156.97 v1(85.57,156.84) 85.5,156.78 85.5,155 85.57,154.94 85.57,154.15 U2.D5 ; v1(80.23,72.39) 80.18,72.34 U22.30 ; v1(65.5,134.11) 62.58,131.19 62.58,122.94 63.6,121.92 66.52,121.92 68.04,120.4 68.04,120.14 v1(68.17,120.02)
  BOTTOM w0.127: v1(85.57,156.84) 85.31,157.1 80.99,157.1 75.66,151.76 75.66,144.83 75.18,144.35 75.18,142.93 72.94,140.69 72.26,140.69 66.19,134.62 66.01,134.62 v1(65.5,134.11) 64.99,133.6 54.71,133.6 v1(54.45,133.35) 53.94,132.84 50.01,132.84 49.88,132.72 49.37,132.72 48.74,133.35 38.45,133.35 32.86,127.76 v1(29.69,127.76) ; v1(68.17,120.02) 68.17,119.51 67.02,118.36 67.02,113.28 74.64,105.66 74.64,101.35 72.36,99.06 72.36,94.11 75.28,91.19 75.28,84.1 77.08,82.3 77.08,76.99 74.34,74.24 74.34,72.19 74.9,71.63 79.47,71.63 v1(80.23,72.39)
D4: length 175.2
  TOP w0.127: v1(98.11,131.06) 99.7,131.06 CN7.10 ; U2.E5 86.33,154.17 86.33,154.69 86.46,154.81 86.46,155.19 87.85,156.59 91.41,156.59 92.75,155.24 92.75,154.91 93.44,154.23 v1(94.41,154.23) 94.76,154.58 95.73,154.58 96.44,155.3 96.44,156.24 98.29,158.09 103.68,158.09 105.12,156.64 105.12,155.27 106.09,154.31 106.09,150.7 107,149.78 107,149.1 107.36,148.74 107.36,146.81 107.11,146.56 105.95,146.56 U5.H5 ; U22.32 79.18,70.19 79.4,69.98 v1(79.47,69.98) ; v1(76.68,130.43) 75.91,130.43 75.63,130.15 U7.58 73.6,130.15 73.5,130.05 72.49,130.05 71.34,128.91 71.34,123.44 72.49,122.3 72.49,121.54 v1(72.74,121.28)
  BOTTOM w0.127: v1(72.74,121.28) 72.23,120.78 72.23,119.76 71.72,119.25 71.72,117.35 71.22,116.84 71.22,114.81 75.66,110.36 76.68,110.36 78.07,108.97 78.07,105.16 79.98,103.25 79.98,88.06 85.49,82.55 85.49,74.35 82.39,71.25 80.74,71.25 v1(79.47,69.98) ; v1(94.41,154.23) 94.33,154.15 94.33,153.77 93.9,153.34 93.9,151.82 92.81,150.72 92.81,150.7 91.33,149.22 89.07,149.22 88.41,148.56 84.91,148.56 83.41,147.07 83.41,138.23 80.64,135.46 79.24,135.46 76.04,132.26 76.04,131.06 v1(76.68,130.43) 76.8,130.3 96.54,130.3 96.77,130.53 97.58,130.53 v1(98.11,131.06)
D5: length 167.7
  TOP w0.102: 103.17,151.13 103.17,150.53 103.07,150.43 103.07,148.65 102.84,148.42 102.84,147.9 102.45,147.52 U5.E5
  TOP w0.127: v1(96.84,131.06) 96.34,131.57 CN7.9 ; v1(76.68,131.06) 75.91,131.06 75.5,130.65 U7.59 73.59,130.65 73.5,130.56 73.37,130.56 73.25,130.43 72.23,130.43 70.83,129.03 70.83,123.19 71.22,122.81 71.22,122.56 71.85,121.92 v1(71.85,121.41) ; 103.17,151.13 103.17,151.18 102.81,151.54 102.81,153.44 104.16,154.79 104.16,156.49 103.32,157.33 98.75,157.33 97.2,155.78 97.2,154.94 95.93,153.67 95.19,153.67 94.68,153.16 v1(94.38,153.16) 93.39,153.16 91.92,154.64 91.92,154.97 91.21,155.68 89.78,155.68 89.4,156.06 88.06,156.06 87.09,155.09 87.09,154.43 86.69,154.03 U2.F5 ; v1(78.68,69.98) U22.33
  BOTTOM w0.127: v1(71.85,121.41) 71.85,120.02 71.34,119.51 71.34,117.6 70.83,117.09 70.83,114.55 75.41,109.98 76.42,109.98 77.69,108.71 77.69,104.9 79.6,103 79.6,87.76 85.11,82.25 85.11,74.6 82.14,71.63 80.36,71.63 78.71,69.98 v1(78.68,69.98) ; v1(96.84,131.06) 96.74,131.06 96.36,130.68 77.31,130.68 76.93,131.06 v1(76.68,131.06) 76.68,132.08 79.67,135.08 80.82,135.08 83.79,138.05 83.79,146.89 85.08,148.18 88.59,148.18 89.25,148.84 91.61,148.84 94.38,151.61 v1(94.38,153.16)
D6: length 167
  TOP w0.127: U2.F6 86.71,154.55 86.71,155.04 87.95,156.29 89.5,156.29 89.73,156.06 91.38,156.06 92.3,155.14 92.3,154.81 93.36,153.75 94.58,153.75 94.96,154.13 v1(95.65,154.13) 95.83,154.13 96.82,155.12 96.82,156.06 98.47,157.71 103.5,157.71 104.74,156.46 104.74,155.09 105.71,154.13 105.71,150.55 106.78,149.48 106.78,148.77 106.98,148.56 106.98,148.08 106.7,147.8 105.7,147.8 U5.H6 ; CN7.8 98.93,132.84 v1(98.16,132.08) ; v1(71.34,120.27) 71.34,121.79 70.33,122.81 70.33,129.16 72.1,130.94 73.25,130.94 73.46,131.15 U7.60 75.11,131.15 75.53,131.57 v1(77.18,131.57) ; v1(77.68,72.39) U22.35
  BOTTOM w0.127: v1(77.68,72.39) 79.08,73.79 79.72,73.79 82.52,76.58 82.52,81.33 79.22,84.63 79.22,93.85 77.82,95.25 77.82,104.14 77.31,104.65 77.31,108.46 76.17,109.6 75.15,109.6 70.45,114.3 70.45,117.35 70.96,117.86 70.96,120.02 71.22,120.27 v1(71.34,120.27) ; v1(98.16,132.08) 97.61,131.52 91.48,131.52 91.03,131.06 77.69,131.06 v1(77.18,131.57) 77.18,131.95 79.93,134.7 81.07,134.7 84.17,137.79 84.17,146.71 85.26,147.8 88.77,147.8 89.43,148.46 91.79,148.46 94.94,151.61 94.94,153.42 v1(95.65,154.13)
D7: length 162
  TOP w0.102: 102.66,151.13 102.84,150.95 102.84,148.81 102.45,148.42 U5.E6
  TOP w0.127: 102.66,151.13 102.43,151.36 102.43,153.62 103.78,154.97 103.78,156.31 103.14,156.95 99,156.95 97.58,155.52 97.58,154.76 95.98,153.16 v1(95.55,153.16) 95.55,152.96 95.24,152.65 93.24,152.65 91.54,154.36 91.54,154.79 91.03,155.3 89.81,155.3 89.3,155.8 88.16,155.8 87.47,155.12 87.47,154.56 U2.G6 ; U22.36 77.18,72.77 77.69,73.28 v1(77.69,73.41) ; v1(79.22,132.72) 78.96,132.97 78.07,132.97 77.75,132.65 U7.63 73.18,132.65 69.82,129.29 69.82,122.68 70.83,121.67 v1(70.83,121.41) ; v1(96.92,131.98) 96.77,131.98 95.9,132.84 CN7.7
  BOTTOM w0.127: v1(95.55,153.16) 95.55,152.6 95.6,152.55 95.6,148.84 94.84,148.08 89.6,148.08 88.94,147.42 85.44,147.42 84.55,146.53 84.55,137.62 81.25,134.32 80.18,134.32 79.22,133.35 v1(79.22,132.72) 79.22,132.59 80.36,131.44 90.65,131.44 91.18,131.98 v1(96.92,131.98) ; v1(70.83,121.41) 70.83,120.52 70.58,120.27 70.58,118.11 70.07,117.6 70.07,114.05 76.93,107.19 76.93,104.39 77.44,103.89 77.44,95.02 78.84,93.62 78.84,84.43 82.14,81.13 82.14,76.83 79.47,74.17 78.45,74.17 v1(77.69,73.41)
D8: length 149.7
  TOP w0.102: U5.F3 103.88,145.49 v4(103.88,145.49)
  TOP w0.127: v1(85.11,145.41) 85.11,145.52 83.28,147.35 83.28,150.4 83.66,150.78 U2.B1 ; v1(70.07,121.54) 70.07,121.79 69.31,122.56 69.31,129.41 73.04,133.15 U7.64 77.62,133.15 77.82,133.35 79.22,133.35 v1(79.85,132.72) ; v1(98.11,132.84) 98.11,133.02 99.21,134.11 CN7.6 ; v1(76.68,72.39) U22.37
  BOTTOM w0.127: v1(76.68,72.39) 76.7,72.39 77.18,72.87 77.18,73.61 80.41,76.83 80.41,82.25 78.45,84.2 78.45,93.37 77.06,94.77 77.06,103.63 76.55,104.14 76.55,106.93 68.93,114.55 68.93,117.09 70.2,118.36 70.2,120.52 70.45,120.78 70.45,120.9 70.07,121.28 v1(70.07,121.54) ; v4(103.88,145.49) 104.36,145.01 104.36,144.35 104.01,143.99 104.01,142.62 103.09,141.71 101.37,141.71 100.58,142.49 98.01,142.49 96.36,144.15 96.36,145.67 94.33,147.7 89.78,147.7 89.12,147.04 85.62,147.04 85.11,146.53 v1(85.11,145.41) 85.11,145.36 84.93,145.19 84.93,137.44 81.43,133.93 80.44,133.93 79.85,133.35 v1(79.85,132.72) 80.11,132.46 81.12,132.46 81.76,131.83 90.39,131.83 91.03,132.46 97.73,132.46 v1(98.11,132.84)
D9: length 147.6
  TOP w0.127: U5.G3 104.49,145.06 v4(104.96,144.59) ; v1(80.49,132.97) 79.72,133.73 77.57,133.73 77.48,133.65 U7.65 72.91,133.65 68.47,129.21 68.47,122.76 69.56,121.67 69.56,121.16 v1(69.82,120.9) ; U2.C1 84.3,150.63 84.3,150.5 84.04,150.24 84.04,149 85.54,147.5 85.54,146.35 v1(85.57,146.33) ; U22.38 76.18,73.04 76.47,73.33 v1(76.68,73.33) ; v1(96.87,132.92) 96.87,133.12 95.88,134.11 CN7.5
  BOTTOM w0.127: v1(69.82,120.9) 69.82,118.62 68.55,117.35 68.55,114.3 76.17,106.68 76.17,99.82 75.28,98.93 75.28,95.12 77.95,92.46 77.95,84.07 80.03,81.99 80.03,77.04 76.68,73.69 v1(76.68,73.33) ; v4(104.96,144.59) 104.96,144.3 104.29,143.62 104.29,142.34 103.27,141.33 101.19,141.33 100.4,142.11 97.73,142.11 95.98,143.87 95.98,145.41 94.08,147.32 89.96,147.32 89.27,146.63 85.87,146.63 v1(85.57,146.33) 85.57,144.5 85.31,144.25 85.31,137.26 81.6,133.55 80.69,133.55 80.49,133.35 v1(80.49,132.97) 80.61,132.84 81.3,132.84 81.93,132.21 90.14,132.21 90.85,132.92 v1(96.87,132.92)
D10: length 150.9
  TOP w0.127: v1(75.41,72.39) 75.18,72.16 U22.40 ; v1(86.53,144.91) 86.53,145.11 86.1,145.54 86.1,147.5 84.55,149.05 84.55,150.37 84.8,150.62 84.8,151.17 U2.C2 ; v1(68.93,121.54) 68.93,121.67 68.04,122.56 68.04,129.41 72.77,134.15 U7.66 76.89,134.15 76.93,134.11 80.36,134.11 81.25,133.22 81.76,133.22 v1(81.88,133.1) ; v1(97.86,133.43) 97.86,134.16 99.08,135.38 CN7.4 ; U5.F4 103.45,146.05 103.02,145.62 102.23,145.62 101.95,145.34 101.95,142.98 102.3,142.62 102.3,141.88 102.08,141.66 102.08,140.92 v4(102.03,140.87)
  BOTTOM w0.127: v1(68.93,121.54) 69.31,121.16 69.31,120.78 69.44,120.65 69.44,118.87 68.17,117.6 68.17,114.05 75.79,106.43 75.79,100.08 74.9,99.19 74.9,94.87 75.91,93.85 75.91,93.78 77.57,92.13 77.57,83.9 79.65,81.81 79.65,77.32 76.04,73.71 76.04,73.03 v1(75.41,72.39) ; v4(102.03,140.87) 101.09,140.87 100.22,141.73 97.56,141.73 95.6,143.69 95.6,145.16 93.82,146.94 90.14,146.94 88.74,145.54 88.74,145.52 88.41,145.19 86.81,145.19 v1(86.53,144.91) 85.69,144.07 85.69,137.08 81.88,133.27 v1(81.88,133.1) 81.88,132.82 82.11,132.59 89.88,132.59 90.72,133.43 v1(97.86,133.43)
D11: length 144.5
  TOP w0.102: U5.G4 104.88,145.62 v4(104.88,145.58)
  TOP w0.127: CN7.3 93.11,135.38 92.81,135.08 92.81,134.04 v1(92.83,134.01) ; U2.D2 85.19,151.34 85.57,150.96 85.57,150.11 85.19,149.73 85.19,148.97 86.48,147.68 86.48,145.72 87.45,144.75 v1(87.45,144.7) ; v1(84.04,133.48) 83.92,133.6 81.5,133.6 80.61,134.49 77.69,134.49 77.54,134.65 U7.67 72.64,134.65 67.66,129.67 67.66,122.3 68.42,121.54 68.42,121.28 v1(68.8,120.9) ; U22.41 74.68,72.4 v1(75.56,73.28)
  BOTTOM w0.127: v1(68.8,120.9) 68.93,120.78 68.93,120.52 69.06,120.4 69.06,119.13 67.79,117.86 67.79,113.79 75.41,106.17 75.41,100.33 74.52,99.44 74.52,94.61 76.04,93.09 76.04,93.04 77.18,91.9 77.18,83.62 77.87,82.93 77.87,76.5 75.66,74.3 75.66,73.41 75.56,73.3 v1(75.56,73.28) ; v4(104.88,145.58) 105.4,145.06 105.4,144.36 104.67,143.62 104.67,142.11 102.97,140.41 100.98,140.41 100.04,141.35 97.38,141.35 95.22,143.51 95.22,144.91 93.57,146.56 90.34,146.56 88.49,144.7 v1(87.45,144.7) 86.07,143.33 86.07,136.91 84.04,134.87 v1(84.04,133.48) 84.3,133.22 89.88,133.22 90.6,133.93 92.75,133.93 v1(92.83,134.01)
D12: length 151
  TOP w0.102: 87.34,149.99 87.34,150.16 87.22,150.29 87.22,150.37 87.05,150.53 87.05,150.9 86.81,151.14 86.58,151.14 86.2,151.53 U2.E2 ; v4(103.89,146.62) U5.F5
  TOP w0.127: v1(74.8,73.25) 74.64,73.1 74.64,73.03 74.14,72.52 74.06,72.52 73.68,72.14 U22.43 ; v1(92.6,137.29) 92.86,137.54 98.27,137.54 99.16,136.65 CN7.2 ; 87.34,149.99 87.34,149.73 89.91,147.17 89.91,144.32 v1(90.09,144.15) ; v1(88.11,137.29) 85.06,134.24 81.5,134.24 80.87,134.87 77.95,134.87 77.67,135.15 U7.68 72.5,135.15 67.28,129.92 67.28,122.05 67.91,121.41 67.91,121.16 v1(68.04,121.03)
  BOTTOM w0.127: v1(68.04,121.03) 68.04,120.78 68.68,120.14 68.68,119.38 67.41,118.11 67.41,113.54 75.03,105.92 75.03,101.09 72.74,98.81 72.74,94.49 76.8,90.42 76.8,83.36 77.49,82.68 77.49,76.76 75.28,74.55 75.28,73.79 74.8,73.3 v1(74.8,73.25) ; v4(103.89,146.62) 103.89,146.62 104.45,146.05 105.01,146.05 105.71,145.35 105.71,144.16 105.05,143.5 105.05,141.94 103.14,140.03 100.81,140.03 99.87,140.97 97.12,140.97 94.84,143.26 94.84,144.65 93.31,146.18 90.57,146.18 90.09,145.69 v1(90.09,144.15) 90.01,144.15 86.46,140.59 86.46,138.43 87.6,137.29 v1(88.11,137.29) v1(92.6,137.29)
D13: length 163.1
  TOP w0.127: U5.G6 104.45,148.07 104.84,148.46 105.94,148.46 v4(105.96,148.49) ; U2.F2 86.88,151.53 87.23,151.18 87.6,151.18 87.8,150.98 87.8,150.67 88.23,150.24 88.23,150.06 90.77,147.52 90.77,145.75 v1(90.75,145.72) ; U22.44 73.18,72.33 72.87,72.64 v1(72.87,72.77) ; 60.96,80.64 62.81,82.5 68.9,82.5 71.27,84.86 83.36,84.86 84.4,85.9 84.4,86.87 85.08,87.55 85.08,88.49 v1(85.06,88.52)
  BOTTOM w0.127: v1(85.06,88.52) 85.57,88.01 86.33,88.01 86.71,88.39 94.08,88.39 94.96,89.28 98.65,89.28 102.71,93.34 102.71,98.3 104.49,100.08 104.49,108.33 104.11,108.71 104.11,136.91 105.81,138.61 106.5,138.61 107.72,139.83 107.72,141.86 108.43,142.57 108.43,147.65 107.16,148.92 106.39,148.92 v4(105.96,148.49) 105.96,144.02 105.43,143.48 105.43,141.76 103.24,139.57 100.68,139.57 99.66,140.59 96.87,140.59 94.46,143 94.46,144.4 93.06,145.8 90.9,145.8 90.82,145.72 v1(90.75,145.72) ; 60.96,80.64 60.96,80.64 62.07,79.53 62.07,78.21 68.52,71.75 71.85,71.75 v1(72.87,72.77)
D14: length 156.9
  TOP w0.127: v1(93.95,142.24) 93.47,142.72 90.62,142.72 89.53,143.81 89.53,146.81 86.96,149.38 86.96,150.24 86.69,150.51 U2.F1 ; v1(71.6,72.77) 71.6,72.64 72.18,72.06 U22.46 ; 63.5,80.64 64.95,82.09 69.13,82.09 71.49,84.45 83.74,84.45 84.78,85.5 84.78,86.69 85.57,87.48 85.57,89.15 v1(85.06,89.66) ; U5.F6 104.05,147.46 106.61,147.46 106.88,147.19 v1(106.9,147.19)
  BOTTOM w0.127: v1(93.95,142.24) 93.95,142.11 96.23,139.83 99.23,139.83 100.25,138.81 103.6,138.81 106.19,141.4 106.19,142.52 106.9,143.23 106.9,144.42 106.55,144.78 106.55,146.84 v1(106.9,147.19) 106.9,147.2 106.91,147.21 107.4,147.21 107.66,146.94 107.66,142.93 106.95,142.21 106.95,140.18 106.14,139.37 105.3,139.37 103.35,137.41 103.35,108.2 103.73,107.82 103.73,100.58 101.82,98.68 101.82,95.63 98.9,92.71 98.9,90.93 98.01,90.04 94.46,90.04 93.57,89.15 85.57,89.15 v1(85.06,89.66) ; v1(71.6,72.77) 71.09,72.26 70.07,72.26 64.87,77.47 64.87,78.36 63.5,79.72 63.5,80.64
D15: length 151
  TOP w0.127: U5.G7 104.97,149.58 106.22,149.58 106.45,149.35 106.45,148.51 v4(106.57,148.39) ; U22.47 71.68,71.92 70.83,72.77 v1(70.71,72.77) ; v1(93.95,142.98) 93.82,143.1 91.15,143.1 90.8,143.46 90.8,144.37 90.29,144.88 90.29,147.35 89.76,147.88 89.76,147.96 87.85,149.86 87.85,149.99 87.44,150.4 U2.G1 ; 66.04,80.64 66.04,81.06 66.69,81.71 69.39,81.71 71.75,84.07 84.07,84.07 85.16,85.17 85.16,86.51 86.07,87.43 v1(86.07,88.52)
  BOTTOM w0.102: 106.9,148.39 v4(106.57,148.39)
  BOTTOM w0.127: v4(106.57,148.39) 106.27,148.08 106.27,143.94 105.81,143.48 105.81,141.58 103.42,139.19 100.43,139.19 99.41,140.21 96.62,140.21 93.95,142.88 v1(93.95,142.98) ; 106.9,148.39 107.03,148.39 108.05,147.37 108.05,142.75 107.33,142.04 107.33,140 106.32,138.99 105.56,138.99 103.73,137.16 103.73,108.46 104.11,108.08 104.11,100.33 102.2,98.42 102.2,95.38 99.28,92.46 99.28,90.68 98.27,89.66 94.71,89.66 93.82,88.77 86.33,88.77 v1(86.07,88.52) ; 66.04,80.64 66.04,79.72 67.41,78.36 67.41,75.82 70.45,72.77 v1(70.71,72.77)
E5V: length 49.4
  TOP w0.508: 14.52,38.99 C100.1 ; C100.1 17.24,37.29 ; C100.1 17.24,40.69 ; L2.3 4.48,37.83 ; L2.3 4.48,35.49 ; L2.3 3.32,36.66 ; L2.3 5.65,36.66 ; JP17.8 4.79,64.64 4.79,67.18 7.97,70.36 9.49,70.36 10.18,71.04 D5.1
  BOTTOM w0.508: JP17.8 3.52,37.62 L2.3
I2C_SCL: length 330.8
  TOP w0.127: v1(42.51,111.51) 42.49,111.51 42.26,111.73 42.26,118.62 39.21,121.67 39.21,127.25 39.85,127.89 44.29,127.89 R60.1 R61.1 ; v1(85.31,22.61) 86.71,22.61 87.22,22.1 88.36,22.1 88.88,21.58 U32.4 ; v1(43.28,66.7) 43.3,66.7 44.67,68.07 54.32,68.07 55.09,68.83 82.87,68.83 84.14,70.1 v1(118.59,70.1) ; U29.H1 82.74,33.5 83.18,33.5 v1(83.49,33.81) ; v1(119.35,145.41) 118.71,144.78 CN3.3 ; U33.19 79.68,22.02 v1(79.6,22.1)
  BOTTOM w0.127: v1(119.35,145.41) 119.53,145.24 119.53,129.84 115.28,125.6 115.28,95.2 119.25,91.24 119.25,70.76 v1(118.59,70.1) ; v1(42.51,111.51) 42.41,111.4 41.68,111.4 34.69,104.42 34.69,93.68 36.16,92.2 36.16,92.18 36.67,91.67 36.67,72.01 41.75,66.93 43.05,66.93 v1(43.28,66.7) 43.35,66.7 43.61,66.45 43.61,46.46 53.56,36.5 67.28,36.5 70.53,39.75 75.16,39.75 77.94,36.96 77.94,35.62 79.5,34.06 81.41,34.06 81.74,34.39 82.91,34.39 83.49,33.82 v1(83.49,33.81) 85.69,31.61 85.69,22.99 v1(85.31,22.61) 84.68,21.97 79.72,21.97 v1(79.6,22.1)
I2C_SDA: length 333.2
  TOP w0.089: 80.99,33.53 80.99,33.52 80.99,32.24 U29.F3
  TOP w0.127: CN3.1 121.25,144.02 120.36,144.91 v1(120.36,145.41) ; v1(78.45,21.72) 78.84,21.34 78.84,20.7 79.23,20.31 U33.20 ; U32.5 87.74,20.44 86.46,21.72 v1(85.69,21.72) ; R58.1 R57.1 44.16,128.14 39.59,128.14 38.96,127.51 38.96,121.54 42.01,118.49 42.01,110.49 v1(42.39,110.11) ; v1(44.32,66.52) 44.32,66.57 45.56,67.82 54.45,67.82 55.21,68.58 83.15,68.58 84.3,69.72 118.33,69.72 118.46,69.6 118.71,69.6 v1(119.22,70.1) ; 80.99,33.53 80.99,34.67 80.93,34.73 v1(80.93,34.74)
  BOTTOM w0.127: v1(120.36,145.41) 119.93,144.98 119.93,129.74 115.54,125.35 115.54,95.53 119.5,91.57 119.5,70.38 v1(119.22,70.1) ; v1(78.45,21.72) 78.58,21.59 85.57,21.59 v1(85.69,21.72) 86.38,22.4 86.38,31.8 83.43,34.74 v1(80.93,34.74) 79.4,34.74 78.68,35.46 78.68,36.66 75.21,40.13 70.35,40.13 67.1,36.88 53.56,36.88 44.32,46.13 v1(44.32,66.52) 43.53,67.31 41.88,67.31 36.93,72.26 36.93,93.98 36.72,94.18 36.72,105.56 41.14,109.98 42.26,109.98 v1(42.39,110.11)
IRDA_RX: length 21.8
  TOP w0.127: v1(3.4,96.39) 3.49,96.49 U11.4
  BOTTOM w0.127: JP15.4 13.43,83.31 10.89,83.31 3.27,90.93 3.27,96.27 v1(3.4,96.39)
LCD_CSN: length 47.8
  TOP w0.127: v1(56.48,66.65) 56.89,67.06 89.38,67.06 93.81,62.62 CN19.1
  BOTTOM w0.127: SB46.2 SB47.2 57.37,65.76 v1(56.48,66.65)
LCD_D0: length 23.3
  TOP w0.127: CN19.6 99.73,56.01 96.74,56.01 90.14,62.61 82.51,62.61 82.18,62.94 U22.23
LCD_D1: length 21
  TOP w0.127: CN19.7 98.72,54.99 96.87,54.99 89.63,62.23 82.39,62.23 81.68,62.94 U22.22
LCD_D2: length 25.5
  TOP w0.127: CN19.8 100.24,53.98 97.12,53.98 89.25,61.85 82.39,61.85 81.63,62.61 80.87,62.61 80.68,62.8 U22.20
LCD_D3: length 23.6
  TOP w0.127: U22.19 80.18,62.92 80.74,62.36 81.38,62.36 82.26,61.47 88.49,61.47 97.5,52.46 CN19.9
LCD_D4: length 28.1
  TOP w0.127: CN19.10 100.18,51.38 97.94,51.38 88.23,61.09 82.14,61.09 81.12,62.1 79.98,62.1 79.18,62.9 U22.17
LCD_D5: length 26.3
  TOP w0.127: U22.16 78.68,62.64 79.47,61.85 80.99,61.85 82.14,60.71 87.94,60.71 CN19.11
LCD_D6: length 30.5
  TOP w0.127: CN19.12 100.36,49.01 98.41,49.01 86.96,60.45 81.88,60.45 80.87,61.47 79.09,61.47 77.68,62.88 U22.14
LCD_D7: length 28.7
  TOP w0.127: U22.13 77.18,62.87 78.84,61.21 80.61,61.21 81.76,60.07 86.03,60.07 CN19.13
LCD_D8: length 32.7
  TOP w0.127: U22.12 76.68,62.86 78.58,60.96 80.36,60.96 81.63,59.69 85.11,59.69 98.52,46.28 100.17,46.28 CN19.14
LCD_D9: length 31
  TOP w0.127: CN19.15 84.25,59.31 81.38,59.31 79.98,60.71 78.07,60.71 76.18,62.6 U22.11
LCD_D10: length 35.2
  TOP w0.127: U22.9 75.18,62.84 77.69,60.33 79.85,60.33 81.12,59.05 83.13,59.05 98.39,43.79 100.22,43.79 CN19.16
LCD_D11: length 33.7
  TOP w0.127: CN19.17 98.72,42.85 82.9,58.67 81.12,58.67 79.85,59.94 77.57,59.94 74.68,62.83 U22.8
LCD_D12: length 41.3
  TOP w0.127: CN19.18 100.19,41.22 98.19,41.22 97.38,42.04 97.38,43.69 82.9,58.17 81.25,58.17 79.85,59.56 73.88,59.56 72.74,60.71 72.74,61.8 73.68,62.74 U22.6
LCD_D13: length 39.4
  TOP w0.127: CN19.19 98.7,39.78 98.7,40.2 97,41.91 97,43.43 82.65,57.78 81.12,57.78 79.72,59.18 73.76,59.18 72.49,60.45 72.49,62.1 73.18,62.8 U22.5
LCD_D14: length 43.5
  TOP w0.127: U22.3 72.18,60.25 73.63,58.8 79.62,58.8 81.15,57.28 82.65,57.28 96.55,43.37 96.55,41.72 97.63,40.64 97.63,39.5 98.41,38.72 99.14,38.72 100.18,39.76 CN19.20
LCD_D15: length 42.1
  TOP w0.127: CN19.21 98.72,37.92 97.33,39.32 97.33,40.44 96.04,41.72 96.04,43.4 82.54,56.9 81.05,56.9 79.52,58.42 73.37,58.42 71.68,60.11 U22.2
LCD_NE3_BUF: length 33.9
  TOP w0.127: R161.2 82.68,73.19 U22.25 82.68,70.27 81.83,69.42 74.06,69.42 73.25,70.23 71.47,70.23 71.18,70.52 U22.48 71.18,71.76 70.86,72.09 66.52,72.09 65.98,72.62 59.2,72.62 v1(58.97,72.39)
  BOTTOM w0.127: v1(58.97,72.39) 57.93,72.39 57.12,71.58 SB48.2 SB49.2
LCD_RDN: length 50.9
  TOP w0.127: U21.6 55.39,64.36 57.58,66.55 88.74,66.55 96.11,59.18 100.37,59.18 CN19.4
LCD_RS: length 51.9
  TOP w0.127: v1(54.45,66.04) 54.78,66.04 56.05,67.31 89.76,67.31 93.06,64.01 99.88,64.01 CN19.2
  BOTTOM w0.127: SB44.2 SB45.2 54.45,65.02 v1(54.45,66.04)
LCD_RSTN: length 47.7
  TOP w0.127: U21.8 56.39,64.68 58.01,66.29 88.36,66.29 97.12,57.54 CN19.5
LCD_WRN: length 48.4
  TOP w0.127: U21.5 54.89,64.4 57.3,66.8 89,66.8 95.73,60.07 98.72,60.07 CN19.3
LCDCOM0: length 56.6
  TOP w0.127: v1(57.59,124.54) 56.86,125.26 56.86,130.64 58.75,132.53 U7.100
  BOTTOM w0.127: CN11.3 36.44,96.77 36.44,105.79 41.55,110.9 42.69,110.9 44.42,112.62 48.58,112.62 55.85,119.89 55.85,122.4 57.59,124.14 v1(57.59,124.54)
LCDCOM1: length 59.5
  TOP w0.127: U7.101 58.25,132.41 56.61,130.77 56.61,124.67 v1(56.83,124.45)
  BOTTOM w0.127: CN11.1 32,96.91 32,98.8 32.56,99.36 32.56,107.11 41.27,115.82 42.94,115.82 45.62,115.82 47.33,117.53 47.33,118.54 47.64,118.86 48.05,118.86 48.05,118.86 51.15,118.86 56.12,123.83 56.12,123.99 56.58,124.45 v1(56.83,124.45)
LCDCOM2: length 75.8
  TOP w0.127: v1(42.13,107.7) 41.5,108.33 41.5,118.11 38.32,121.28 38.32,128.52 46.07,136.27 46.07,146.18 47.21,147.32 55.09,147.32 55.98,146.43 55.98,141.48 56.99,140.46 57.5,140.46 57.75,140.21 U7.102
  BOTTOM w0.127: CN11.5 38.96,96.74 38.96,104.52 v1(42.13,107.7)
LCDCOM3: length 34.5
  TOP w0.127: v1(44.04,106.53) 44.93,107.42 44.93,120.27 45.82,121.16 49.75,121.16 50.24,121.65 U7.140
  BOTTOM w0.127: CN11.7 40.64,96.37 41.55,97.28 41.55,104.01 44.04,106.5 v1(44.04,106.53)
LCDCOM4: length 83
  TOP w0.127: v1(56.57,123.81) 55.7,124.68 55.7,130.71 56.92,131.94 56.92,134.56 55.34,136.15 U7.111 ; CN14.7 39.12,76.58 36.14,76.58 v1(36.04,76.68)
  BOTTOM w0.127: v1(36.04,76.68) 36.42,77.06 36.42,81.79 35.15,83.06 35.15,92.08 33.9,93.32 33.9,107.16 41.17,114.43 47.19,114.43 v1(56.57,123.81)
LCDCOM5: length 86.5
  TOP w0.127: v1(30.98,78.05) 30.98,77.29 31.82,76.45 34.82,76.45 35.53,77.17 36.11,77.17 37.05,78.11 CN14.5 ; v1(55.25,126.49) 55.21,126.53 55.21,130.61 56.54,131.94 56.54,134.12 55.02,135.65 U7.112
  BOTTOM w0.127: v1(55.25,126.49) 54.01,126.49 51.39,123.88 51.39,123.26 51.13,123 49.92,123 49.6,122.68 46.56,122.68 43,119.13 40.46,119.13 29.53,108.2 29.53,100.28 29.32,100.08 29.31,100.08 28.92,99.69 28.92,93.07 30.78,91.21 30.78,78.38 30.98,78.18 v1(30.98,78.05)
LCDCOM6: length 81.1
  TOP w0.127: CN14.3 34.54,77.09 32.1,77.09 31.79,77.39 31.79,78.28 v1(31.46,78.61) ; v1(55.01,125.84) 54.58,126.27 54.58,130.88 55.91,132.21 55.91,133.76 54.53,135.15 U7.113
  BOTTOM w0.127: v1(55.01,125.84) 54.99,125.86 54.27,125.86 52.03,123.61 52.03,123 51.19,122.16 50.11,122.16 49.79,121.84 46.61,121.84 43.26,118.49 40.72,118.49 30.17,107.93 30.17,100.02 29.58,99.43 29.58,93.33 31.41,91.49 31.41,78.66 v1(31.46,78.61)
LCDCOM7: length 72.3
  TOP w0.127: v1(54.49,125.09) 54.49,125.14 53.94,125.7 53.94,130.61 53.94,131.14 54.57,131.76 54.57,132.16 53.94,132.78 53.94,133.1 53.39,133.65 U7.116
  BOTTOM w0.127: v1(54.49,125.09) 54.37,124.97 54.37,124.28 51.61,121.53 50.37,121.53 49.91,121.07 46.74,121.07 43.9,118.23 43.53,117.86 40.99,117.86 40.42,117.29 40.42,117.2 30.95,107.72 30.95,99.91 30.47,99.43 30.47,93.34 32.07,91.74 32.07,79.05 CN14.1
LCDSEG0: length 44.6
  TOP w0.508: v1(85.44,114.43) 85.31,114.3 82.39,114.3
  BOTTOM w0.508: CN14.47 90.27,79.28 90.27,81.15 87.09,84.33 86.2,84.33 82.9,87.63 82.9,91.31 82.77,91.44 82.77,99.06 83.15,99.44 83.15,101.22 84.55,102.62 84.55,112.39 85.44,113.28 v1(85.44,114.43)
LCDSEG1: length 26.3
  TOP w0.127: v1(82.01,99.69) 82.26,99.44 82.26,97.92 81.88,97.54 81.12,97.54 80.34,96.76 77.07,96.76 CN11.35 ; v1(83.41,115.32) 83.03,115.7 82.39,115.7
  BOTTOM w0.127: v1(82.01,99.69) 81.88,99.82 81.88,101.85 83.41,103.38 v1(83.41,115.32)
LCDSEG2: length 30.8
  TOP w0.508: 82.39,117.09 83.53,117.09 84.68,115.95 v1(84.68,115.32) ; v1(82.39,100.33) 81.25,100.33 80.11,99.19 80.11,97.66 79.78,97.33 75.11,97.33 CN11.33
  BOTTOM w0.508: v1(84.68,115.32) 84.68,113.67 83.92,112.9 83.92,103.25 82.39,101.73 v1(82.39,100.33)
